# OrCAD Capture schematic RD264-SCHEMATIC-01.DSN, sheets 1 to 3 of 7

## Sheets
1 7: size A3
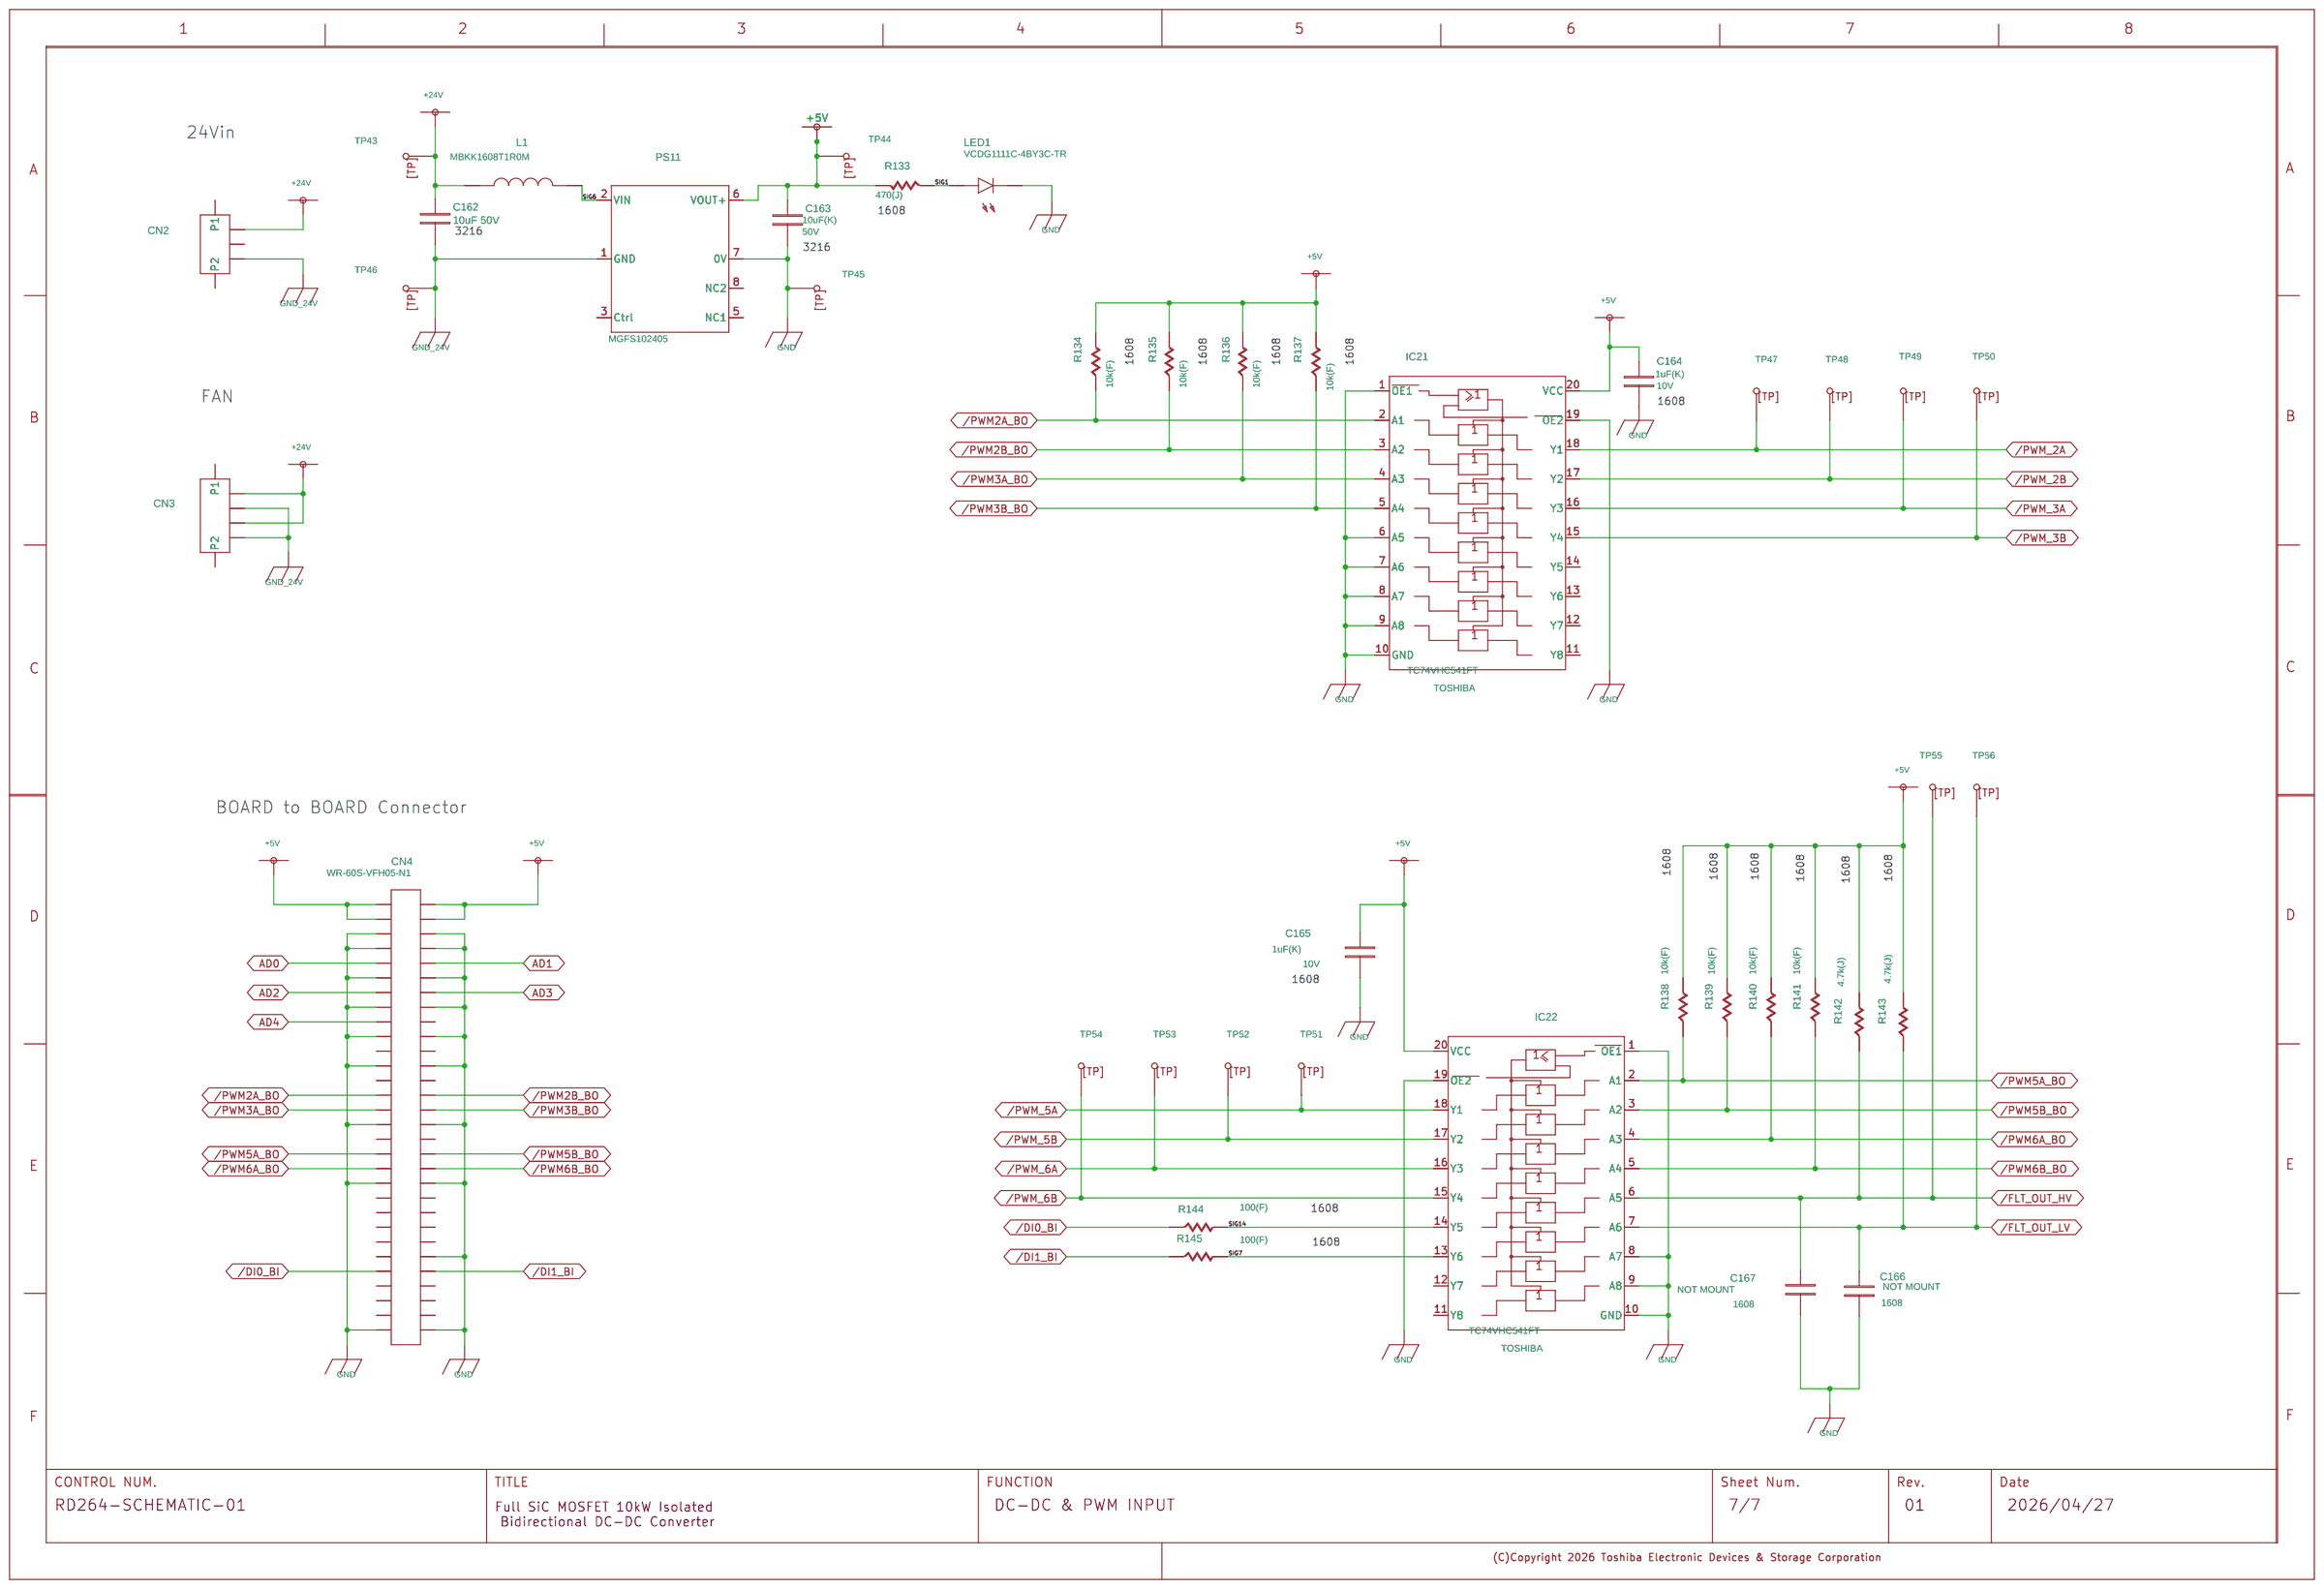
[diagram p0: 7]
2 6: size A3
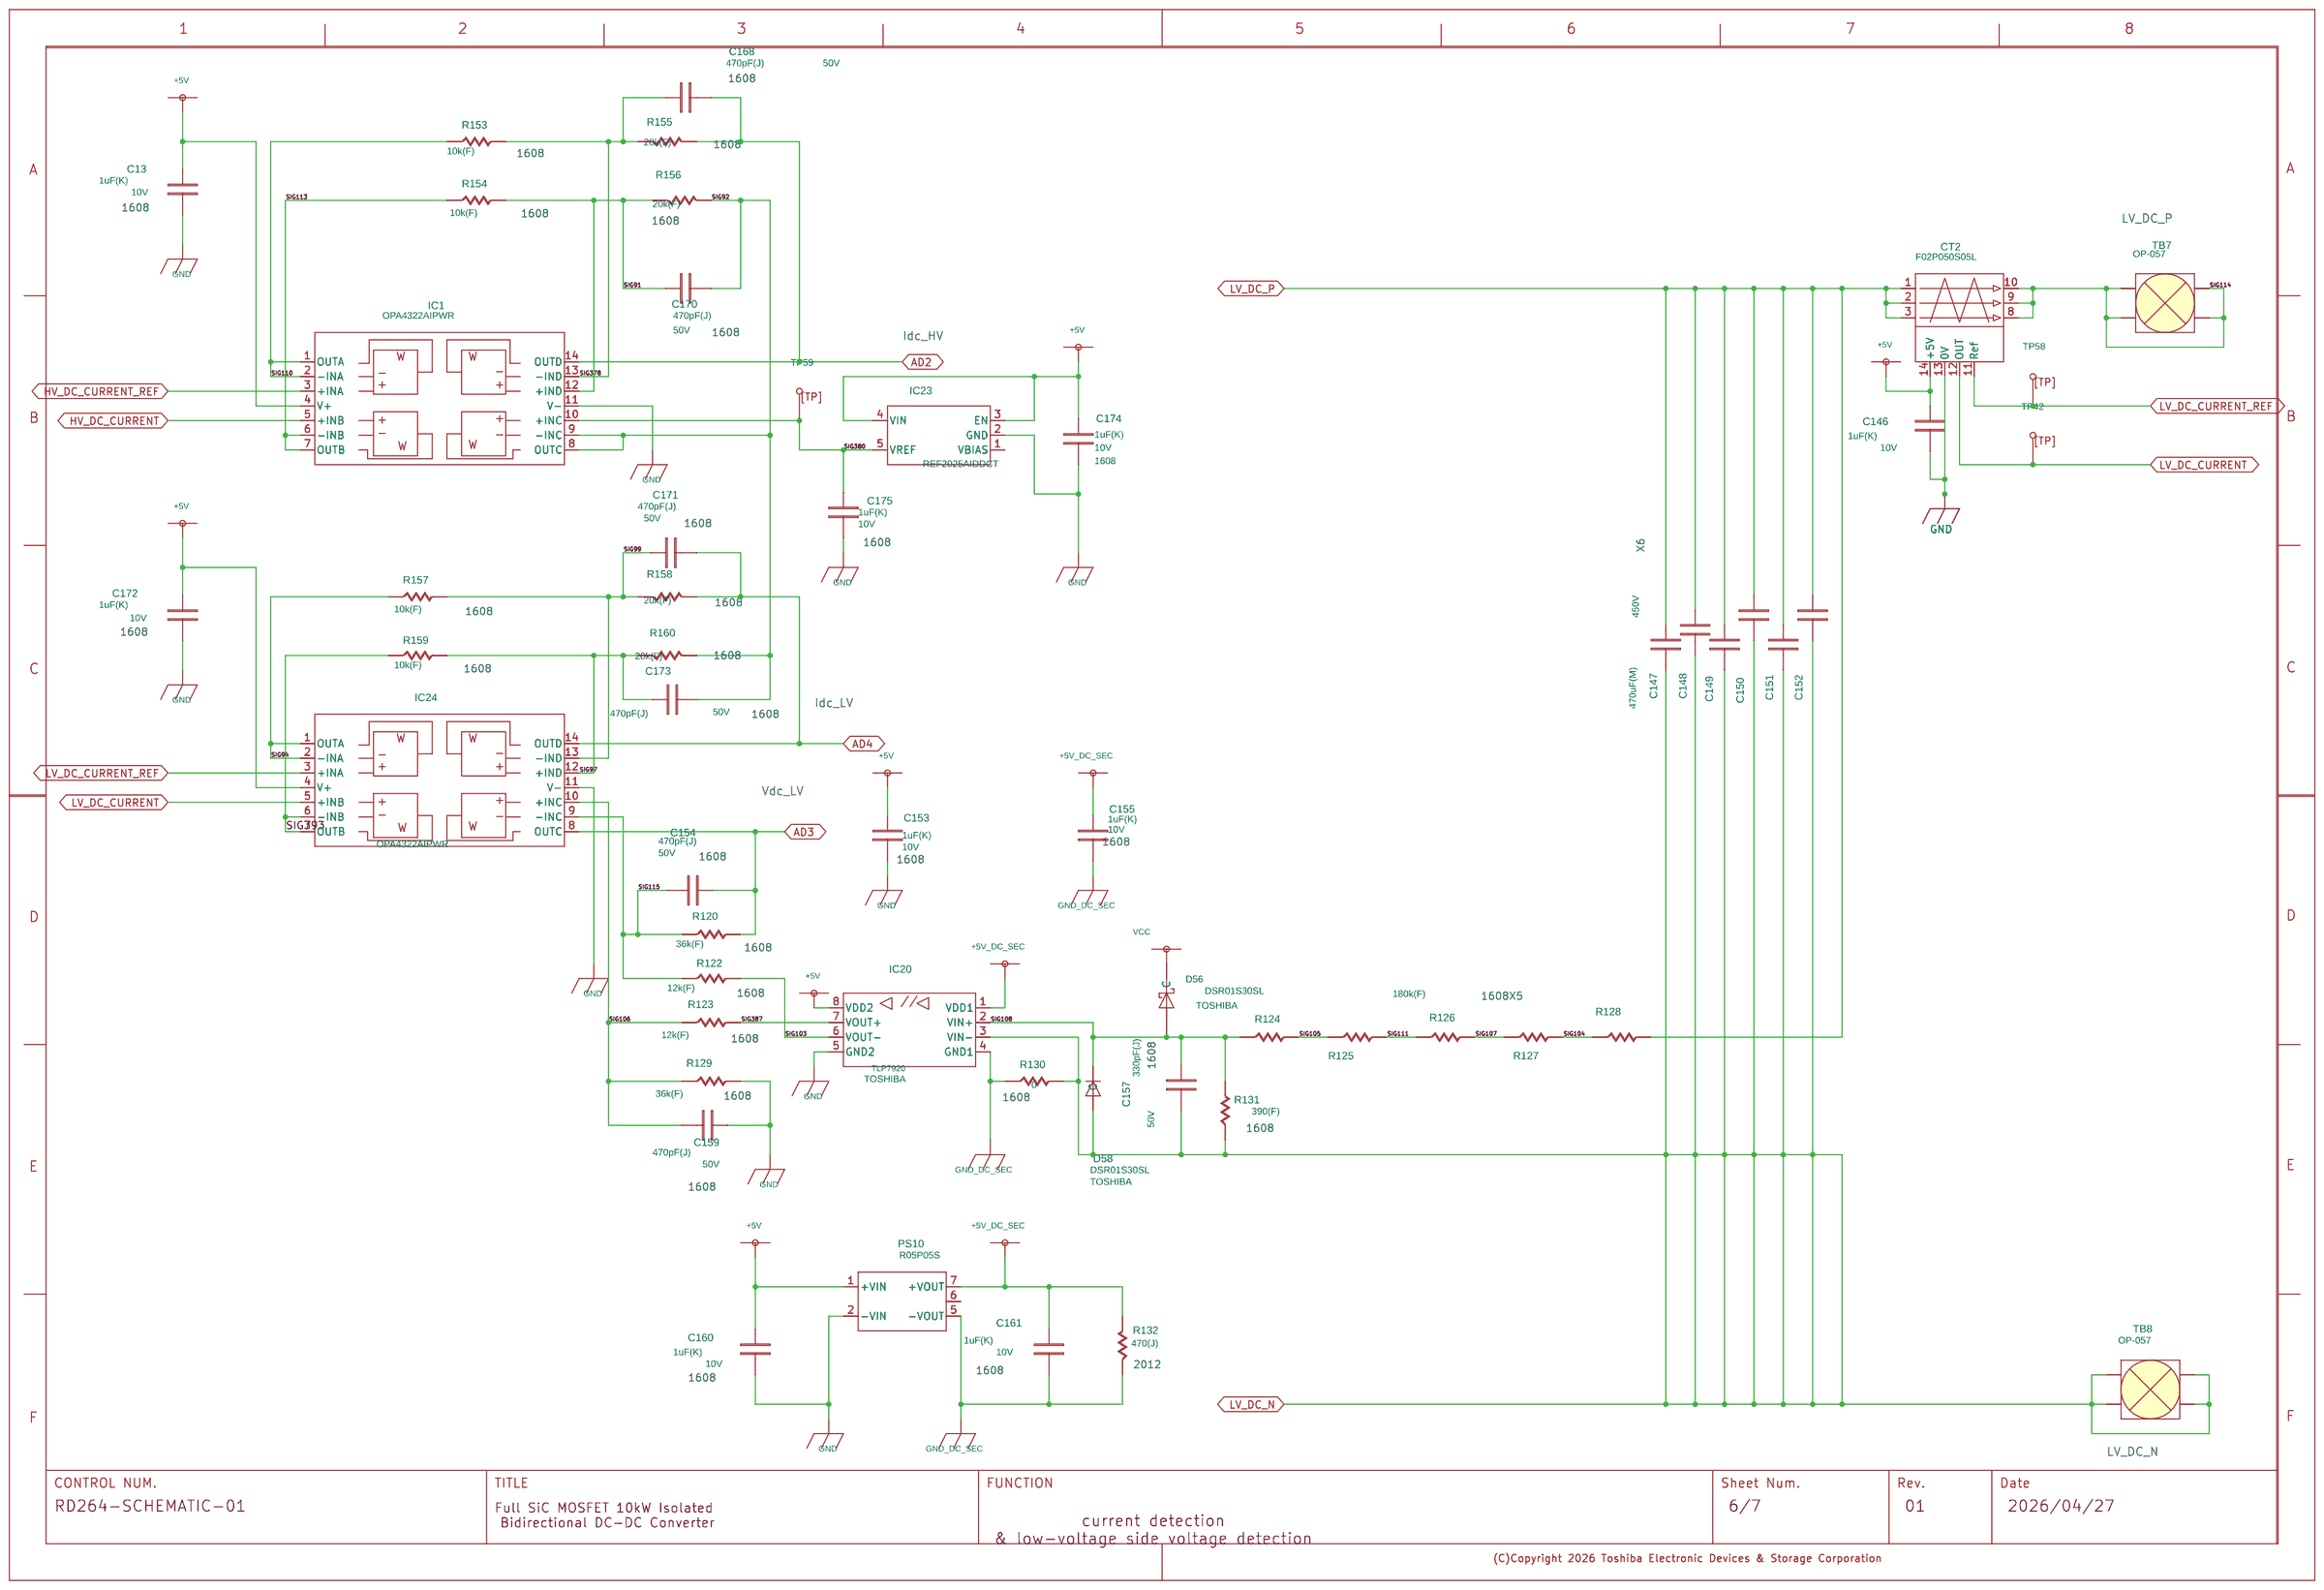
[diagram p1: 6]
3 5: size A3
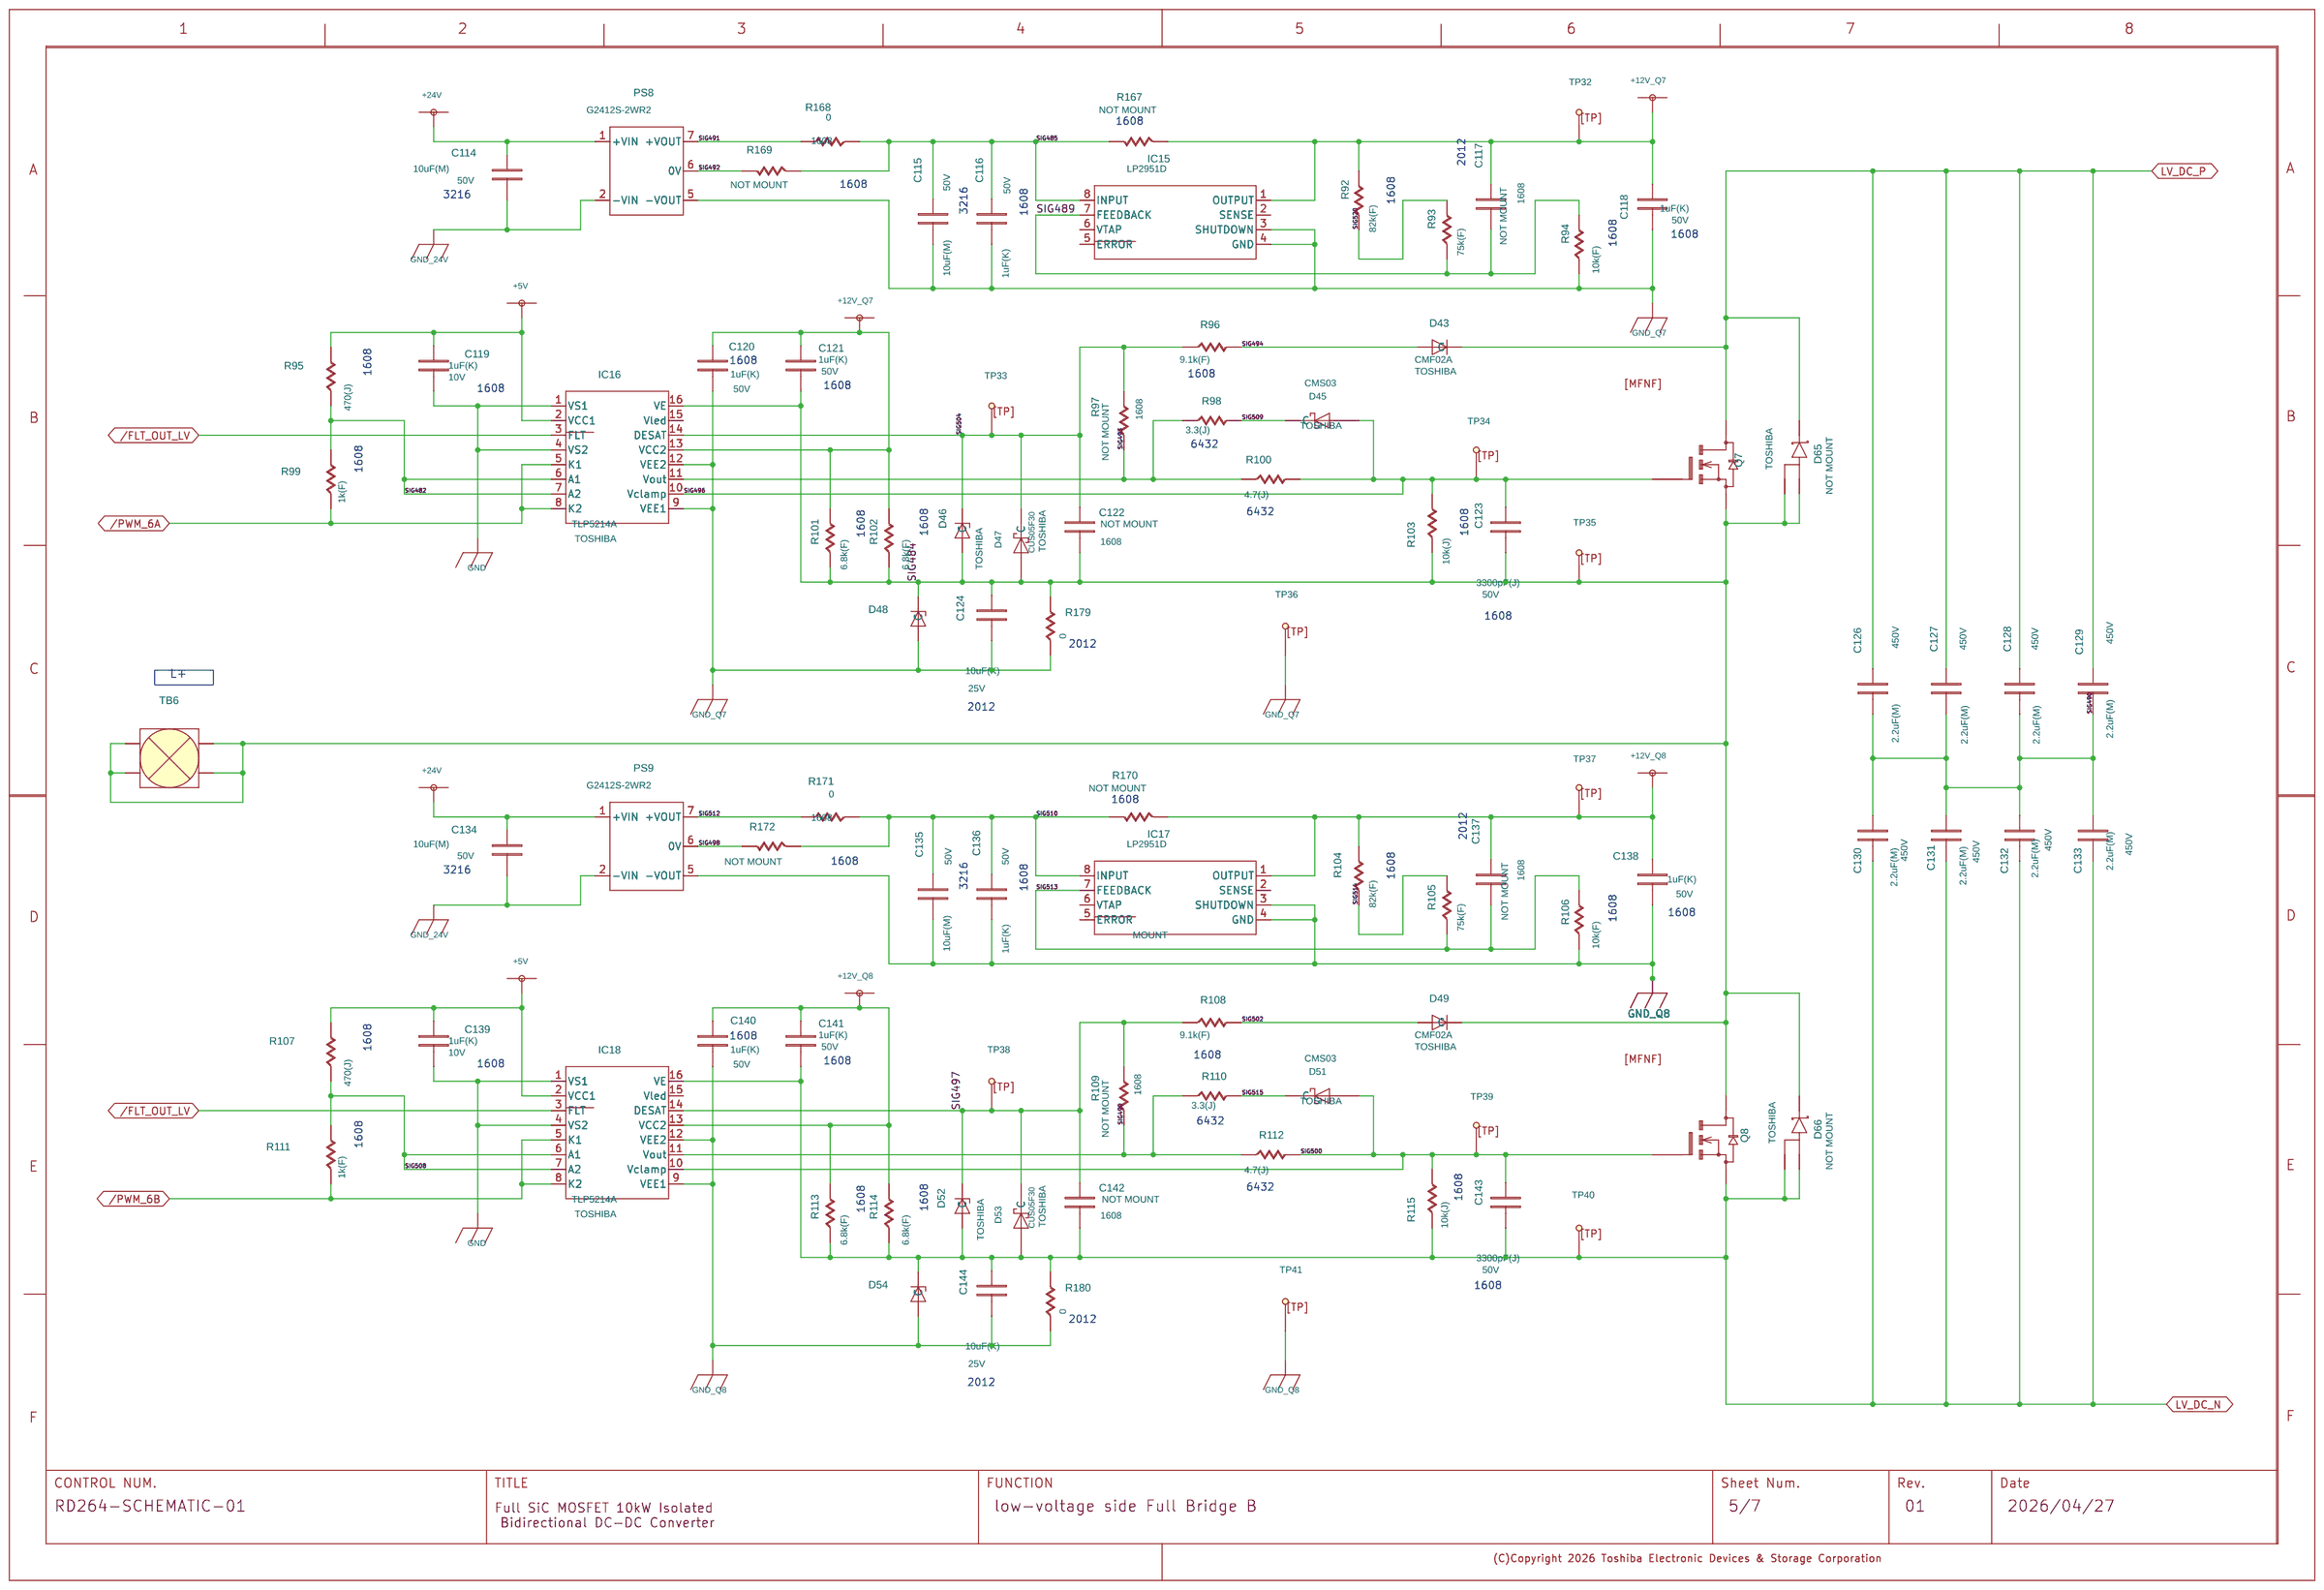
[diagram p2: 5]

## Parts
sheet 5
C114  GRM31CR61H106MA12L
C115  GRM31CR61H106MA12L
C116  GRM188R61H105KAALD
C117  NC_C1608
C118  GRM188R61H105KAALD
C119  GRM188R71A105KA61D
C120  GRM188R61H105KAALD
C121  GRM188R61H105KAALD
C122  NC_C1608
C123  GRM1885C1H682JA01D
C124  GRM21BC71E106KE11L
C126  CKG57NX7T2W225M500JH
C127  CKG57NX7T2W225M500JH
C128  CKG57NX7T2W225M500JH
C129  CKG57NX7T2W225M500JH
C130  CKG57NX7T2W225M500JH
C131  CKG57NX7T2W225M500JH
C132  CKG57NX7T2W225M500JH
C133  CKG57NX7T2W225M500JH
C134  GRM31CR61H106MA12L
C135  GRM31CR61H106MA12L
C136  GRM188R61H105KAALD
C137  NC_C1608
C138  GRM188R61H105KAALD
C139  GRM188R71A105KA61D
C140  GRM188R61H105KAALD
C141  GRM188R61H105KAALD
C142  NC_C1608
C143  GRM1885C1H682JA01D
C144  GRM21BC71E106KE11L
D43  CMF05
D45  SBD
D46  CRY82
D47  SBD
D48  KDZVTR2.0B
D49  CMF05
D51  SBD
D52  CRY82
D53  SBD
D54  KDZVTR2.0B
D65  NC_TO-247
D66  NC_TO-247
IC15  LP2951D
IC16  TLP5214A
IC17  LP2951D
IC18  TLP5214A
PS8  G2412S-2WR2
PS9  G2412S-2WR2
Q7  TK49N65W5
Q8  TK49N65W5
R92  RK73H1JTTD8202F
R93  RK73H1JTTD7502F
R94  RK73H1JTTD1002F
R95  RK73B1JTTD471J
R96  ERJ3EKF9101V
R97  NC_R1608
R98  ERJ1TYJ100U
R99  RK73H1JTTD1001F
R100  ERJ1TYJ470U
R101  RK73H1JTTD6801F
R102  RK73H1JTTD6801F
R103  RK73B1JTTD103J
R104  RK73H1JTTD8202F
R105  RK73H1JTTD7502F
R106  RK73H1JTTD1002F
R107  RK73B1JTTD471J
R108  ERJ3EKF9101V
R109  NC_R1608
R110  ERJ1TYJ100U
R111  RK73H1JTTD1001F
R112  ERJ1TYJ470U
R113  RK73H1JTTD6801F
R114  RK73H1JTTD6801F
R115  RK73B1JTTD103J
R167  RK73Z1JTTD
R168  NC_R1608
R169  RK73Z1JTTD
R170  RK73Z1JTTD
R171  NC_R1608
R172  RK73Z1JTTD
R179  RK73Z2ATTD
R180  RK73Z2ATTD
TB6  OP-057
TP32  TP
TP33  TP
TP34  TP
TP35  TP
TP36  TP
TP37  TP
TP38  TP
TP39  TP
TP40  TP
TP41  TP
U?#2  WAKU_DEF100
sheet 6
C13  GRM188R71A105KA61D
C146  GRM188R71A105KA61D
C147  ESMR451VSN471MR40S
C148  ESMR451VSN471MR40S
C149  ESMR451VSN471MR40S
C150  ESMR451VSN471MR40S
C151  ESMR451VSN471MR40S
C152  ESMR451VSN471MR40S
C153  GRM188R71A105KA61D
C154  GRM1885C1H471JA01D
C155  GRM188R71A105KA61D
C157  GRM1885C1H331JA01D
C159  GRM1885C1H471JA01D
C160  GRM188R71A105KA61D
C161  GRM188R71A105KA61D
C168  GRM1885C1H471JA01D
C170  GRM1885C1H471JA01D
C171  GRM1885C1H471JA01D
C172  GRM188R71A105KA61D
C173  GRM1885C1H471JA01D
C174  GRM188R71A105KA61D
C175  GRM188R71A105KA61D
CT2  F02P050S05L
D56  SBD
D58  DSR01S30SL
IC1  OPA4322AIPWR
IC20  TLP7920(LF5,TP5)
IC23  REF2025AIDDCT
IC24  OPA4322AIPWR
PS10  R05P05S
R120  RK73G1JTTD3602F
R122  RK73G1JTTD1202F
R123  RK73G1JTTD1202F
R124  ERJ3EKF1803V
R125  ERJ3EKF1803V
R126  ERJ3EKF1803V
R127  ERJ3EKF1803V
R128  ERJ3EKF1803V
R129  RK73G1JTTD3602F
R130  RK73Z1JTTD
R131  RK73G1JTTD3900F
R132  RK73B2ATTD471J
R153  RK73H1JTTD1002F
R154  RK73H1JTTD1002F
R155  RK73H1JTTD2002F
R156  RK73H1JTTD2002F
R157  RK73H1JTTD1002F
R158  RK73H1JTTD2002F
R159  RK73H1JTTD1002F
R160  RK73H1JTTD2002F
TB7  OP-057
TB8  OP-057
TP42  TP
TP58  TP
TP59  TP
U?#1  WAKU_DEF100
sheet 7
C162  GRM31CR61H106KA12L
C163  GRM31CR61H106KA12L
C164  GRM188R71A105KA61D
C165  GRM188R71A105KA61D
C166  NC_C1608
C167  NC_C1608
CN2  BM03B-PASS-TFT(LF)(SN)
CN3  BM04B-PASS-TFT(LF)(SN)
CN4  WR-60S-VFH05-N1
IC21  TC74VHC541FT
IC22  TC74VHC541FT
L1  MBKK1608T1R0M
LED1  VCDG1111C-4BY3C-TR
PS11  MGFS102405
R133  RK73B1JTTD471J
R134  RK73H1JTTD1002F
R135  RK73H1JTTD1002F
R136  RK73H1JTTD1002F
R137  RK73H1JTTD1002F
R138  RK73H1JTTD1002F
R139  RK73H1JTTD1002F
R140  RK73H1JTTD1002F
R141  RK73H1JTTD1002F
R142  RK73B1JTTD472J
R143  RK73B1JTTD472J
R144  ERJ3EKF1000V
R145  ERJ3EKF1000V
TP43  TP
TP44  TP
TP45  TP
TP46  TP
TP47  TP
TP48  TP
TP49  TP
TP50  TP
TP51  TP
TP52  TP
TP53  TP
TP54  TP
TP55  TP
TP56  TP
U?#7  WAKU_DEF100

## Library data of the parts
C114 C134 = C_v2: COMP: C-GRM31CR61H106MA12L; COMPONENTNAME: C_C.Normal_package; COMPONENTTYPE: 4; FUNCN: C_C.Normal_package; INSTANCENAME: INS17112921; NOTE: 10uF 50V; PART TYPE: Ceramic Capacitor; REFERENCE TEMPLATE: C; SIZE: 1; VAL1: 10uF(M); VAL2: 50V
C115 C135 = C_v2: COMP: C-GRM31CR61H106MA12L; COMPONENTNAME: C_C.Normal_package; COMPONENTTYPE: 4; FUNCN: C_C.Normal_package; INSTANCENAME: INS17112929; NOTE: 10uF 50V; PART TYPE: Ceramic Capacitor; REFERENCE TEMPLATE: C; SIZE: 1; VAL1: 10uF(M); VAL2: 50V
C116 C136 = C_v2: COMP: C-GRM188R61H105KAALD; COMPONENTNAME: C_C.Normal_package; COMPONENTTYPE: 4; FUNCN: C_C.Normal_package; INSTANCENAME: INS17112937; NOTE: 1uF 50V; PART TYPE: Ceramic Capacitor; REFERENCE TEMPLATE: C; SIZE: 1; VAL1: 1uF(K); VAL2: 50V
C117 C137 = C_v2: COMP: C-1608_NM; COMPONENTNAME: C_C.Normal_package; COMPONENTTYPE: 4; FUNCN: C_C.Normal_package; INSTANCENAME: INS17112913; NOTMOUNT: NOT MOUNT; PART TYPE: Ceramic Capacitor; REFERENCE TEMPLATE: C; SIZE: 1; SIZECODESMD: 1608
C118 C138 = C_v2: COMP: C-GRM188R61H105KAALD; COMPONENTNAME: C_C.Normal_package; COMPONENTTYPE: 4; FUNCN: C_C.Normal_package; INSTANCENAME: INS17112961; NOTE: 1uF 50V; PART TYPE: Ceramic Capacitor; REFERENCE TEMPLATE: C; SIZE: 1; VAL1: 1uF(K); VAL2: 50V
C119 C139 = C_v2: COMP: C-GRM188R71A105KA61D; COMPONENTNAME: C_C.Normal_package; COMPONENTTYPE: 4; FUNCN: C_C.Normal_package; INSTANCENAME: INS17113085; NOTE: 1uF 10V; PART TYPE: Ceramic Capacitor; REFERENCE TEMPLATE: C; SIZE: 1; VAL1: 1uF(K); VAL2: 10V
C120 C140 = C_v2: COMP: C-GRM188R61H105KAALD; COMPONENTNAME: C_C.Normal_package; COMPONENTTYPE: 4; FUNCN: C_C.Normal_package; INSTANCENAME: INS17113061; NOTE: 1uF 50V; PART TYPE: Ceramic Capacitor; REFERENCE TEMPLATE: C; SIZE: 1; VAL1: 1uF(K); VAL2: 50V
C121 C141 = C_v2: COMP: C-GRM188R61H105KAALD; COMPONENTNAME: C_C.Normal_package; COMPONENTTYPE: 4; FUNCN: C_C.Normal_package; INSTANCENAME: INS17113069; NOTE: 1uF 50V; PART TYPE: Ceramic Capacitor; REFERENCE TEMPLATE: C; SIZE: 1; VAL1: 1uF(K); VAL2: 50V
C122 C142 = C_v2: COMP: C-1608_NM; COMPONENTNAME: C_C.Normal_package; COMPONENTTYPE: 4; FUNCN: C_C.Normal_package; INSTANCENAME: INS17113388; NOTMOUNT: NOT MOUNT; PART TYPE: Ceramic Capacitor; REFERENCE TEMPLATE: C; SIZE: 1; SIZECODESMD: 1608
C123 C143 = C_v2: COMP: C-GRM1885C1H682JA01D; COMPONENTNAME: C_C.Normal_package; COMPONENTTYPE: 4; FUNCN: C_C.Normal_package; INSTANCENAME: INS17753463; NOTE: 6800pF 50V; PART TYPE: Ceramic Capacitor; REFERENCE TEMPLATE: C; SIZE: 1; VAL1: 3300pF(J); VAL2: 50V
C124 C144 = C_v2: COMP: C-GRM21BC71E106KE11L; COMPONENTNAME: C_C.Normal_package; COMPONENTTYPE: 4; FUNCN: C_C.Normal_package; INSTANCENAME: INS17895207; NOTE: 10uF 25V; PART TYPE: Ceramic Capacitor; REFERENCE TEMPLATE: C; SIZE: 1; VAL1: 10uF(K); VAL2: 25V
C126 = C_v2: COMP: C-CKG57NX7T2W225M500JH; COMPONENTNAME: C_C.Normal_package; COMPONENTTYPE: 4; FUNCN: C_C.Normal_package; INSTANCENAME: INS17255321; NOTE: 2.2uF 450V; PART TYPE: Ceramic Capacitor; REFERENCE TEMPLATE: C; SIZE: 1; VAL1: 2.2uF(M); VAL2: 450V
C127 = C_v2: COMP: C-CKG57NX7T2W225M500JH; COMPONENTNAME: C_C.Normal_package; COMPONENTTYPE: 4; FUNCN: C_C.Normal_package; INSTANCENAME: INS17255582; NOTE: 2.2uF 450V; PART TYPE: Ceramic Capacitor; REFERENCE TEMPLATE: C; SIZE: 1; VAL1: 2.2uF(M); VAL2: 450V
C128 = C_v2: COMP: C-CKG57NX7T2W225M500JH; COMPONENTNAME: C_C.Normal_package; COMPONENTTYPE: 4; FUNCN: C_C.Normal_package; INSTANCENAME: INS17255645; NOTE: 2.2uF 450V; PART TYPE: Ceramic Capacitor; REFERENCE TEMPLATE: C; SIZE: 1; VAL1: 2.2uF(M); VAL2: 450V
C129 = C_v2: COMP: C-CKG57NX7T2W225M500JH; COMPONENTNAME: C_C.Normal_package; COMPONENTTYPE: 4; FUNCN: C_C.Normal_package; INSTANCENAME: INS17255762; NOTE: 2.2uF 450V; PART TYPE: Ceramic Capacitor; REFERENCE TEMPLATE: C; SIZE: 1; VAL1: 2.2uF(M); VAL2: 450V
C130 = C_v2: COMP: C-CKG57NX7T2W225M500JH; COMPONENTNAME: C_C.Normal_package; COMPONENTTYPE: 4; FUNCN: C_C.Normal_package; INSTANCENAME: INS17255916; NOTE: 2.2uF 450V; PART TYPE: Ceramic Capacitor; REFERENCE TEMPLATE: C; SIZE: 1; VAL1: 2.2uF(M); VAL2: 450V
C131 = C_v2: COMP: C-CKG57NX7T2W225M500JH; COMPONENTNAME: C_C.Normal_package; COMPONENTTYPE: 4; FUNCN: C_C.Normal_package; INSTANCENAME: INS17256105; NOTE: 2.2uF 450V; PART TYPE: Ceramic Capacitor; REFERENCE TEMPLATE: C; SIZE: 1; VAL1: 2.2uF(M); VAL2: 450V
C132 = C_v2: COMP: C-CKG57NX7T2W225M500JH; COMPONENTNAME: C_C.Normal_package; COMPONENTTYPE: 4; FUNCN: C_C.Normal_package; INSTANCENAME: INS17256431; NOTE: 2.2uF 450V; PART TYPE: Ceramic Capacitor; REFERENCE TEMPLATE: C; SIZE: 1; VAL1: 2.2uF(M); VAL2: 450V
C133 = C_v2: COMP: C-CKG57NX7T2W225M500JH; COMPONENTNAME: C_C.Normal_package; COMPONENTTYPE: 4; FUNCN: C_C.Normal_package; INSTANCENAME: INS17256618; NOTE: 2.2uF 450V; PART TYPE: Ceramic Capacitor; REFERENCE TEMPLATE: C; SIZE: 1; VAL1: 2.2uF(M); VAL2: 450V
D43 D49 = D: COMP: D-CMF05; COMPONENTNAME: D_D.Normal_package; COMPONENTTYPE: 4; FUNCN: D_D.Normal_package; INSTANCENAME: INS17279788; USERCOMPTEXT3: TOSHIBA; VAL3: CMF02A
D45 D51 = SBD: COMP: CMS03; COMPONENTTYPE: 4; USERCOMPTEXT3: TOSHIBA; VAL3: CMS03
D46 D52 = ZD: COMP: D-CRY82; COMPONENTNAME: ZD_ZD.Normal_package; COMPONENTTYPE: 4; FUNCN: ZD_ZD.Normal_package; INSTANCENAME: INS17317417; USERCOMPTEXT3: TOSHIBA
D47 D53 = SBD: COMP: CUS05F30; COMPONENTTYPE: 4; USERCOMPTEXT3: TOSHIBA; VAL3: CUS05F30
D48 D54 = ZD: COMP: D-KDZVTR2.0B; COMPONENTNAME: ZD_ZD.Normal_package; COMPONENTTYPE: 4; FUNCN: ZD_ZD.Normal_package; INSTANCENAME: INS17385836; PART TYPE: Zener diode; REFERENCE TEMPLATE: D
D65 D66 = NC_TO_247: COMP: D-TO-247_NM; COMPONENTNAME: NC_TO-247_NC_TO-247.Normal_package; COMPONENTTYPE: 4; FUNCN: NC_TO-247_NC_TO-247.Normal_package; INSTANCENAME: INS17322987; NOTMOUNT: NOT MOUNT; SAVECOUNT: 1; UPDATEDATE: 2020/05/13; UPDATETIME: 14:31:25; VAL3: TO-247
IC15 IC17 = LP2951D: COMP: IC-LP2951D_NM; COMPONENTTYPE: 4; NOTMOUNT: MOUNT
IC16 IC18 = TLP5214A: COMP: IC-TLP5214A; COMPONENTTYPE: 4; USERCOMPTEXT3: TOSHIBA
PS8 PS9 = G2412S_2WR2: COMP: PS-G2412S-2WR2; COMPONENTTYPE: 4
Q7 Q8 = MFNF: COMP: TW048N65C; COMPONENTNAME: MFNF_MFNF.Normal_package; COMPONENTTYPE: 4; FUNCN: MFNF_MFNF.Normal_package; INSTANCENAME: INS17254361; PART NUMBER: TMP-432; PART TYPE: N-channel  Si power MOSFET; REFERENCE TEMPLATE: Q; USERCOMPTEXT3: TOSHIBA; VAL3: TW048N65C
R92 R104 = R: COMP: R-RK73H1JTTD8202F; COMPONENTNAME: R_R.Normal_package; COMPONENTTYPE: 4; FUNCN: R_R.Normal_package; INSTANCENAME: INS17112901; NOTE: 82kohm 0.1W; VAL1: 82k(F); VAL2: 100mw
R93 R105 = R: COMP: R-RK73H1JTTD7502F; COMPONENTNAME: R_R.Normal_package; COMPONENTTYPE: 4; FUNCN: R_R.Normal_package; INSTANCENAME: INS17112949; NOTE: 75kohm 0.1W; VAL1: 75k(F); VAL2: 100mw
R94 R106 = R: COMP: R-RK73H1JTTD1002F; COMPONENTNAME: R_R.Normal_package; COMPONENTTYPE: 4; FUNCN: R_R.Normal_package; INSTANCENAME: INS17112973; NOTE: 10kohm 0.1W; VAL1: 10k(F); VAL2: 100mw
R95 R107 = R: COMP: R-RK73B1JTTD471J; COMPONENTNAME: R_R.Normal_package; COMPONENTTYPE: 4; FUNCN: R_R.Normal_package; INSTANCENAME: INS17113077; NOTE: 470ohm 0.1W; PART TYPE: Resistor SMD; SIZE: 1; VAL1: 470(J); VAL2: 125mw
R96 R108 = R: COMP: R-ERJ3EKF9101V; COMPONENTNAME: R_R.Normal_package; COMPONENTTYPE: 4; FUNCN: R_R.Normal_package; INSTANCENAME: INS17253791; NOTE: 9.1kohm 0.1W; PART NUMBER: TMP-429; PART TYPE: Resistor SMD; VAL1: 9.1k(F); VAL2: 100mw
R97 R109 = R: COMP: R-1608_NM; COMPONENTNAME: R_R.Normal_package; COMPONENTTYPE: 4; FUNCN: R_R.Normal_package; INSTANCENAME: INS17113188; NOTMOUNT: NOT MOUNT; PART TYPE: Resistor SMD; SIZE: 1; SIZECODESMD: 1608
R98 R110 = R: COMP: R-ERJ1TYJ100U; COMPONENTNAME: R_R.Normal_package; COMPONENTTYPE: 4; FUNCN: R_R.Normal_package; INSTANCENAME: INS17253884; NOTE: 10ohm 1W; PART TYPE: Resistor SMD; SIZE: 1; VAL1: 3.3(J); VAL2: 1w
R99 R111 = R: COMP: R-RK73H1JTTD1001F; COMPONENTNAME: R_R.Normal_package; COMPONENTTYPE: 4; FUNCN: R_R.Normal_package; INSTANCENAME: INS17113262; NOTE: 1.0kohm 0.1W; PART TYPE: Resistor SMD; SIZE: 1; VAL1: 1k(F); VAL2: 125mw
R100 R112 = R: COMP: R-ERJ1TYJ470U; COMPONENTNAME: R_R.Normal_package; COMPONENTTYPE: 4; FUNCN: R_R.Normal_package; INSTANCENAME: INS17753183; NOTE: 47ohm 1W; PART NUMBER: TMP-902; PART TYPE: Resistor SMD; VAL1: 4.7(J); VAL2: 1w
R101 R113 = R: COMP: R-RK73H1JTTD6801F; COMPONENTNAME: R_R.Normal_package; COMPONENTTYPE: 4; FUNCN: R_R.Normal_package; INSTANCENAME: INS17113356; NOTE: 6.8kohm 0.1W; PART TYPE: Resistor SMD; SIZE: 1; VAL1: 6.8k(F); VAL2: 100mw
R102 R114 = R: COMP: R-RK73H1JTTD6801F; COMPONENTNAME: R_R.Normal_package; COMPONENTTYPE: 4; FUNCN: R_R.Normal_package; INSTANCENAME: INS17113364; NOTE: 6.8kohm 0.1W; PART TYPE: Resistor SMD; SIZE: 1; VAL1: 6.8k(F); VAL2: 100mw
R103 R115 = R: COMP: R-RK73B1JTTD103J; COMPONENTNAME: R_R.Normal_package; COMPONENTTYPE: 4; FUNCN: R_R.Normal_package; INSTANCENAME: INS17113334; NOTE: 10kohm 0.1W; PART TYPE: Resistor SMD; SIZE: 1; VAL1: 10k(J); VAL2: 100mw
R167 R170 = R: COMP: R-RK73Z1JTTD; COMPONENTNAME: R_R.Normal_package; COMPONENTTYPE: 4; FUNCN: R_R.Normal_package; INSTANCENAME: INS17390327; NOTE: 0ohm 0.1W; NOTMOUNT: NOT MOUNT; PART TYPE: Resistor SMD; SIZE: 1
R168 = R: COMP: R-1608_NM; COMPONENTNAME: R_R.Normal_package; COMPONENTTYPE: 4; FUNCN: R_R.Normal_package; INSTANCENAME: INS17391865; NOTMOUNT: MOUNT; PART TYPE: Resistor SMD; SIZE: 1; VAL1: 0; VAL3: 1608
R169 R172 = R: COMP: R-RK73Z1JTTD; COMPONENTNAME: R_R.Normal_package; COMPONENTTYPE: 4; FUNCN: R_R.Normal_package; INSTANCENAME: INS17391891; NOTE: 0ohm 0.1W; NOTMOUNT: NOT MOUNT; PART TYPE: Resistor SMD; SIZE: 1
R171 = R: COMP: R-1608_NM; COMPONENTNAME: R_R.Normal_package; COMPONENTTYPE: 4; FUNCN: R_R.Normal_package; INSTANCENAME: INS17391865; NOTMOUNT: MOUNT; PART TYPE: Resistor SMD; SIZE: 1; SIZECODESMD: 1608; VAL1: 0
R179 R180 = R: COMP: R-RK73Z2ATTD; COMPONENTNAME: R_R.Normal_package; COMPONENTTYPE: 4; FUNCN: R_R.Normal_package; INSTANCENAME: INS17894887; NOTE: 0ohm 0.25w; PART TYPE: Resistor SMD; SIZE: 1; VAL1: 0
TB6 = OP_057: COMP: TB-OP-057; COMPONENTNAME: OP-057_OP-057.Normal_package; COMPONENTTYPE: 4; FUNCN: OP-057_OP-057.Normal_package; INSTANCENAME: INS17364097; PART NUMBER: TMP-784; PART TYPE: Terminal Block; REFERENCE TEMPLATE: TB; SAVECOUNT: 1; UPDATETIME: 14:31:25
TP32-TP56 TP58 TP59 = TP: COMP: TP-HK-3-G; COMPONENTTYPE: 4; VAL3: HK-3-G
U?#2 = WAKU_DEF100: COMPONENTTYPE: 2; DATE: 2026/04/27; DRAWINGNUMBER: RD264-SCHEMATIC-01; FUNCTION: low-voltage side Full Bridge B; REVISION: 01; SHEETNUMBER: 5/7; SHTSAVECOUNT: 17; TITLE: Full SiC MOSFET 10kW Isolated / Bidirectional DC-DC Converter; UPDATEDATE: 2026.4.27; UPDATETIME: 14:22:34
C13 C172 = C_v2: COMP: C-GRM188R71A105KA61D; COMPONENTNAME: C_C.Normal_package; COMPONENTTYPE: 4; FUNCN: C_C.Normal_package; INSTANCENAME: INS17335180; NOTE: 1uF 10V; PART TYPE: Ceramic Capacitor; REFERENCE TEMPLATE: C; SIZE: 1; VAL1: 1uF(K); VAL2: 10V
C146 = C_v2: COMP: C-GRM188R71A105KA61D; COMPONENTNAME: C_C.Normal_package; COMPONENTTYPE: 4; FUNCN: C_C.Normal_package; INSTANCENAME: INS17154372; NOTE: 1uF 10V; PART TYPE: Ceramic Capacitor; REFERENCE TEMPLATE: C; SIZE: 1; VAL1: 1uF(K); VAL2: 10V
C147 = C_v2: COMP: C-ESMR451VSN471MR40S; COMPONENTNAME: C_C.Normal_package; COMPONENTTYPE: 4; FUNCN: C_C.Normal_package; INSTANCENAME: INS17110408; NOTE: 470uF 450V; PART TYPE: Aluminum Capacitor; REFERENCE TEMPLATE: C; SIZE: 1; VAL1: 470uF(M); VAL2: 450V
C148 = C_v2: COMP: C-ESMR451VSN471MR40S; COMPONENTNAME: C_C.Normal_package; COMPONENTTYPE: 4; FUNCN: C_C.Normal_package; INSTANCENAME: INS17110416; NOTE: 470uF 450V; PART TYPE: Aluminum Capacitor; REFERENCE TEMPLATE: C; SIZE: 1; VAL1: 470uF(M); VAL2: 450V
C149 = C_v2: COMP: C-ESMR451VSN471MR40S; COMPONENTNAME: C_C.Normal_package; COMPONENTTYPE: 4; FUNCN: C_C.Normal_package; INSTANCENAME: INS17110424; NOTE: 470uF 450V; PART TYPE: Aluminum Capacitor; REFERENCE TEMPLATE: C; SIZE: 1; VAL1: 470uF(M); VAL2: 450V
C150 = C_v2: COMP: C-ESMR451VSN471MR40S; COMPONENTNAME: C_C.Normal_package; COMPONENTTYPE: 4; FUNCN: C_C.Normal_package; INSTANCENAME: INS17110469; NOTE: 470uF 450V; PART TYPE: Aluminum Capacitor; REFERENCE TEMPLATE: C; SIZE: 1; VAL1: 470uF(M); VAL2: 450V
C151 = C_v2: COMP: C-ESMR451VSN471MR40S; COMPONENTNAME: C_C.Normal_package; COMPONENTTYPE: 4; FUNCN: C_C.Normal_package; INSTANCENAME: INS17110477; NOTE: 470uF 450V; PART TYPE: Aluminum Capacitor; REFERENCE TEMPLATE: C; SIZE: 1; VAL1: 470uF(M); VAL2: 450V
C152 = C_v2: COMP: C-ESMR451VSN471MR40S; COMPONENTNAME: C_C.Normal_package; COMPONENTTYPE: 4; FUNCN: C_C.Normal_package; INSTANCENAME: INS17110485; NOTE: 470uF 450V; PART TYPE: Aluminum Capacitor; REFERENCE TEMPLATE: C; SIZE: 1; VAL1: 470uF(M); VAL2: 450V
C153 C155 = C_v2: COMP: C-GRM188R71A105KA61D; COMPONENTNAME: C_C.Normal_package; COMPONENTTYPE: 4; FUNCN: C_C.Normal_package; INSTANCENAME: INS17110613; NOTE: 1uF 10V; PART TYPE: Ceramic Capacitor; REFERENCE TEMPLATE: C; SIZE: 1; VAL1: 1uF(K); VAL2: 10V
C154 = C_v2: COMP: C-GRM1885C1H471JA01D; COMPONENTNAME: C_C.Normal_package; COMPONENTTYPE: 4; FUNCN: C_C.Normal_package; INSTANCENAME: INS17110583; NOTE: 470pF 50V; PART TYPE: Ceramic Capacitor; REFERENCE TEMPLATE: C; SIZE: 1; VAL1: 470pF(J); VAL2: 50V
C157 = C_v2: COMP: C-GRM1885C1H331JA01D; COMPONENTNAME: C_C.Normal_package; COMPONENTTYPE: 4; FUNCN: C_C.Normal_package; INSTANCENAME: INS17110887; NOTE: 330pF 50V; PART TYPE: Ceramic Capacitor; REFERENCE TEMPLATE: C; SIZE: 1; VAL1: 330pF(J); VAL2: 50V
C159 = C_v2: COMP: C-GRM1885C1H471JA01D; COMPONENTNAME: C_C.Normal_package; COMPONENTTYPE: 4; FUNCN: C_C.Normal_package; INSTANCENAME: INS17110939; NOTE: 470pF 50V; PART TYPE: Ceramic Capacitor; REFERENCE TEMPLATE: C; SIZE: 1; VAL1: 470pF(J); VAL2: 50V
C160 = C_v2: COMP: C-GRM188R71A105KA61D; COMPONENTNAME: C_C.Normal_package; COMPONENTTYPE: 4; FUNCN: C_C.Normal_package; INSTANCENAME: INS17111029; NOTE: 1uF 10V; PART TYPE: Ceramic Capacitor; REFERENCE TEMPLATE: C; SIZE: 1; VAL1: 1uF(K); VAL2: 10V
C161 = C_v2: COMP: C-GRM188R71A105KA61D; COMPONENTNAME: C_C.Normal_package; COMPONENTTYPE: 4; FUNCN: C_C.Normal_package; INSTANCENAME: INS17111037; NOTE: 1uF 10V; PART TYPE: Ceramic Capacitor; REFERENCE TEMPLATE: C; SIZE: 1; VAL1: 1uF(K); VAL2: 10V
C168 = C_v2: COMP: C-GRM1885C1H471JA01D; COMPONENTNAME: C_C.Normal_package; COMPONENTTYPE: 4; FUNCN: C_C.Normal_package; INSTANCENAME: INS17330257; NOTE: 470pF 50V; PART TYPE: Ceramic Capacitor; REFERENCE TEMPLATE: C; SIZE: 1; VAL1: 470pF(J); VAL2: 50V
C170 = C_v2: COMP: C-GRM1885C1H471JA01D; COMPONENTNAME: C_C.Normal_package; COMPONENTTYPE: 4; FUNCN: C_C.Normal_package; INSTANCENAME: INS17330365; NOTE: 470pF 50V; PART TYPE: Ceramic Capacitor; REFERENCE TEMPLATE: C; SIZE: 1; VAL1: 470pF(J); VAL2: 50V
C171 = C_v2: COMP: C-GRM1885C1H471JA01D; COMPONENTNAME: C_C.Normal_package; COMPONENTTYPE: 4; FUNCN: C_C.Normal_package; INSTANCENAME: INS17330483; NOTE: 470pF 50V; PART TYPE: Ceramic Capacitor; REFERENCE TEMPLATE: C; SIZE: 1; VAL1: 470pF(J); VAL2: 50V
C173 = C_v2: COMP: C-GRM1885C1H471JA01D; COMPONENTNAME: C_C.Normal_package; COMPONENTTYPE: 4; FUNCN: C_C.Normal_package; INSTANCENAME: INS17330591; NOTE: 470pF 50V; PART TYPE: Ceramic Capacitor; REFERENCE TEMPLATE: C; SIZE: 1; VAL1: 470pF(J); VAL2: 50V
C174 = C_v2: COMP: C-GRM188R71A105KA61D; COMPONENTNAME: C_C.Normal_package; COMPONENTTYPE: 4; FUNCN: C_C.Normal_package; INSTANCENAME: INS17336633; NOTE: 1uF 10V; PART TYPE: Ceramic Capacitor; REFERENCE TEMPLATE: C; SIZE: 1; SIZECODESMD: 1608; VAL1: 1uF(K); VAL2: 10V
C175 = C_v2: COMP: C-GRM188R71A105KA61D; COMPONENTNAME: C_C.Normal_package; COMPONENTTYPE: 4; FUNCN: C_C.Normal_package; INSTANCENAME: INS17330751; NOTE: 1uF 10V; PART TYPE: Ceramic Capacitor; REFERENCE TEMPLATE: C; SIZE: 1; VAL1: 1uF(K); VAL2: 10V
CT2 = F02P050S05L: COMP: CT-F02P050S05L; COMPONENTTYPE: 4
D56 = SBD: COMP: DSR01S30SL; COMPONENTTYPE: 4; USERCOMPTEXT3: TOSHIBA; VAL3: DSR01S30SL
D58 = D: COMP: D-DSR01S30SL; COMPONENTNAME: D_D.Normal_package; COMPONENTTYPE: 4; FUNCN: D_D.Normal_package; INSTANCENAME: INS17313401; NOTE: 30V 0.1A; PART NUMBER: TMP-433; PART TYPE: Schottky barrier Diode; USERCOMPTEXT3: TOSHIBA
IC1 IC24 = OPA4322AIPWR: COMP: IC-OPA4322AIPWR; COMPONENTTYPE: 4
IC20 = TLP7920_LF5: COMP: IC-TLP7920_LF5_TP5; COMPONENTTYPE: 4; USERCOMPTEXT3: TOSHIBA; VAL3: TLP7920
IC23 = REF2025AIDDCT: COMP: IC-REF2025AIDDCT; COMPONENTTYPE: 4
PS10 = R05P05S: COMP: PS-R05P05S; COMPONENTTYPE: 4
R120 = R: COMP: R-RK73G1JTTD3602F; COMPONENTNAME: R_R.Normal_package; COMPONENTTYPE: 4; FUNCN: R_R.Normal_package; INSTANCENAME: INS17110637; NOTE: 36kohm 0.1W; VAL1: 36k(F); VAL2: 100mw
R122 = R: COMP: R-RK73G1JTTD1202F; COMPONENTNAME: R_R.Normal_package; COMPONENTTYPE: 4; FUNCN: R_R.Normal_package; INSTANCENAME: INS17110687; NOTE: 12kohm 0.1W; VAL1: 12k(F); VAL2: 100mw
R123 = R: COMP: R-RK73G1JTTD1202F; COMPONENTNAME: R_R.Normal_package; COMPONENTTYPE: 4; FUNCN: R_R.Normal_package; INSTANCENAME: INS17110773; NOTE: 12kohm 0.1W; VAL1: 12k(F); VAL2: 100mw
R124 = R: COMP: R-ERJ3EKF1803V; COMPONENTNAME: R_R.Normal_package; COMPONENTTYPE: 4; FUNCN: R_R.Normal_package; INSTANCENAME: INS17190846; NOTE: 180kohm 0.1W; PART TYPE: Resistor SMD; SIZE: 1; VAL1: 180k(F); VAL2: 100mw
R125 = R: COMP: R-ERJ3EKF1803V; COMPONENTNAME: R_R.Normal_package; COMPONENTTYPE: 4; FUNCN: R_R.Normal_package; INSTANCENAME: INS17190954; NOTE: 180kohm 0.1W; PART TYPE: Resistor SMD; SIZE: 1; VAL1: 180k(F); VAL2: 100mw
R126 = R: COMP: R-ERJ3EKF1803V; COMPONENTNAME: R_R.Normal_package; COMPONENTTYPE: 4; FUNCN: R_R.Normal_package; INSTANCENAME: INS17191012; NOTE: 180kohm 0.1W; PART TYPE: Resistor SMD; SIZE: 1; VAL1: 180k(F); VAL2: 100mw
R127 = R: COMP: R-ERJ3EKF1803V; COMPONENTNAME: R_R.Normal_package; COMPONENTTYPE: 4; FUNCN: R_R.Normal_package; INSTANCENAME: INS17191162; NOTE: 180kohm 0.1W; PART TYPE: Resistor SMD; SIZE: 1; VAL1: 180k(F); VAL2: 100mw
R128 = R: COMP: R-ERJ3EKF1803V; COMPONENTNAME: R_R.Normal_package; COMPONENTTYPE: 4; FUNCN: R_R.Normal_package; INSTANCENAME: INS17191255; NOTE: 180kohm 0.1W; PART TYPE: Resistor SMD; SIZE: 1; VAL1: 180k(F); VAL2: 100mw
R129 = R: COMP: R-RK73G1JTTD3602F; COMPONENTNAME: R_R.Normal_package; COMPONENTTYPE: 4; FUNCN: R_R.Normal_package; INSTANCENAME: INS17110865; NOTE: 36kohm 0.1W; VAL1: 36k(F); VAL2: 100mw
R130 = R: COMP: R-RK73Z1JTTD; COMPONENTNAME: R_R.Normal_package; COMPONENTTYPE: 4; FUNCN: R_R.Normal_package; INSTANCENAME: INS17110931; NOTE: 0ohm 0.1W; PART TYPE: Resistor SMD; SIZE: 1; VAL1: 0
R131 = R: COMP: R-RK73G1JTTD3900F; COMPONENTNAME: R_R.Normal_package; COMPONENTTYPE: 4; FUNCN: R_R.Normal_package; INSTANCENAME: INS17191487; NOTE: 390ohm 0.1W; PART TYPE: Resistor SMD; SIZE: 1; VAL1: 390(F); VAL2: 100mw
R132 = R: COMP: R-RK73B2ATTD471J; COMPONENTNAME: R_R.Normal_package; COMPONENTTYPE: 4; FUNCN: R_R.Normal_package; INSTANCENAME: INS17417097; NOTE: 470ohm 0.25W; PART TYPE: Resistor SMD; SIZE: 1; VAL1: 470(J); VAL2: 250mw
R153 = R: COMP: R-RK73H1JTTD1002F; COMPONENTNAME: R_R.Normal_package; COMPONENTTYPE: 4; FUNCN: R_R.Normal_package; INSTANCENAME: INS17356570; NOTE: 10kohm 0.1W; VAL1: 10k(F); VAL2: 100mw
R154 = R: COMP: R-RK73H1JTTD1002F; COMPONENTNAME: R_R.Normal_package; COMPONENTTYPE: 4; FUNCN: R_R.Normal_package; INSTANCENAME: INS17356638; NOTE: 10kohm 0.1W; VAL1: 10k(F); VAL2: 100mw
R155 = R: COMP: R-RK73H1JTTD2002F; COMPONENTNAME: R_R.Normal_package; COMPONENTTYPE: 4; FUNCN: R_R.Normal_package; INSTANCENAME: INS17357275; NOTE: 20kohm 0.1W; VAL1: 20k(F); VAL2: 100mw
R156 = R: COMP: R-RK73H1JTTD2002F; COMPONENTNAME: R_R.Normal_package; COMPONENTTYPE: 4; FUNCN: R_R.Normal_package; INSTANCENAME: INS17357383; NOTE: 20kohm 0.1W; VAL1: 20k(F); VAL2: 100mw
R157 = R: COMP: R-RK73H1JTTD1002F; COMPONENTNAME: R_R.Normal_package; COMPONENTTYPE: 4; FUNCN: R_R.Normal_package; INSTANCENAME: INS17356770; NOTE: 10kohm 0.1W; VAL1: 10k(F); VAL2: 100mw
R158 = R: COMP: R-RK73H1JTTD2002F; COMPONENTNAME: R_R.Normal_package; COMPONENTTYPE: 4; FUNCN: R_R.Normal_package; INSTANCENAME: INS17357470; NOTE: 20kohm 0.1W; VAL1: 20k(F); VAL2: 100mw
R159 = R: COMP: R-RK73H1JTTD1002F; COMPONENTNAME: R_R.Normal_package; COMPONENTTYPE: 4; FUNCN: R_R.Normal_package; INSTANCENAME: INS17356836; NOTE: 10kohm 0.1W; VAL1: 10k(F); VAL2: 100mw
R160 = R: COMP: R-RK73H1JTTD2002F; COMPONENTNAME: R_R.Normal_package; COMPONENTTYPE: 4; FUNCN: R_R.Normal_package; INSTANCENAME: INS17357529; NOTE: 20kohm 0.1W; VAL1: 20k(F); VAL2: 100mw
TB7 = OP_057: COMP: TB-OP-057; COMPONENTNAME: OP-057_OP-057.Normal_package; COMPONENTTYPE: 4; FUNCN: OP-057_OP-057.Normal_package; INSTANCENAME: INS17364473; PART NUMBER: TMP-784; PART TYPE: Terminal Block; REFERENCE TEMPLATE: TB; SAVECOUNT: 1; UPDATETIME: 14:31:25
TB8 = OP_057: COMP: TB-OP-057; COMPONENTNAME: OP-057_OP-057.Normal_package; COMPONENTTYPE: 4; FUNCN: OP-057_OP-057.Normal_package; INSTANCENAME: INS17364565; PART NUMBER: TMP-784; PART TYPE: Terminal Block; REFERENCE TEMPLATE: TB; SAVECOUNT: 1; UPDATETIME: 14:31:25
U?#1 = WAKU_DEF100: COMPONENTTYPE: 2; DATE: 2026/04/27; DRAWINGNUMBER: RD264-SCHEMATIC-01; FUNCTION: current detection / & low-voltage side voltage detection; REVISION: 01; SHEETNUMBER: 6/7; SHTSAVECOUNT: 15; TITLE: Full SiC MOSFET 10kW Isolated / Bidirectional DC-DC Converter; UPDATEDATE: 2026.4.27; UPDATETIME: 14:22:34
C162 = C_v2: COMP: C-GRM31CR61H106KA12L; COMPONENTNAME: C_C.Normal_package; COMPONENTTYPE: 4; FUNCN: C_C.Normal_package; INSTANCENAME: INS17108792; NOTE: 10uF 50V; PART TYPE: Ceramic Capacitor; REFERENCE TEMPLATE: C; SIZE: 1; VAL1: 10uF(K); VAL2: 50V
C163 = C_v2: COMP: C-GRM31CR61H106KA12L; COMPONENTNAME: C_C.Normal_package; COMPONENTTYPE: 4; FUNCN: C_C.Normal_package; INSTANCENAME: INS17108358; NOTE: 10uF 50V; PART TYPE: Ceramic Capacitor; REFERENCE TEMPLATE: C; SIZE: 1; VAL1: 10uF(K); VAL2: 50V
C164 = C_v2: COMP: C-GRM188R71A105KA61D; COMPONENTNAME: C_C.Normal_package; COMPONENTTYPE: 4; FUNCN: C_C.Normal_package; INSTANCENAME: INS17108750; NOTE: 1uF 10V; PART TYPE: Ceramic Capacitor; REFERENCE TEMPLATE: C; SIZE: 1; VAL1: 1uF(K); VAL2: 10V
C165 = C_v2: COMP: C-GRM188R71A105KA61D; COMPONENTNAME: C_C.Normal_package; COMPONENTTYPE: 4; FUNCN: C_C.Normal_package; INSTANCENAME: INS17108480; NOTE: 1uF 10V; PART TYPE: Ceramic Capacitor; REFERENCE TEMPLATE: C; SIZE: 1; VAL1: 1uF(K); VAL2: 10V
C166 = C_v2: COMP: C-1608_NM; COMPONENTNAME: C_C.Normal_package; COMPONENTTYPE: 4; FUNCN: C_C.Normal_package; INSTANCENAME: INS17108770; NOTMOUNT: NOT MOUNT; PART TYPE: Ceramic Capacitor; REFERENCE TEMPLATE: C; SIZE: 1; SIZECODESMD: 1608
C167 = C_v2: COMP: C-1608_NM; COMPONENTNAME: C_C.Normal_package; COMPONENTTYPE: 4; FUNCN: C_C.Normal_package; INSTANCENAME: INS17108347; NOTMOUNT: NOT MOUNT; PART TYPE: Ceramic Capacitor; REFERENCE TEMPLATE: C; SIZE: 1; SIZECODESMD: 1608
CN2 = BM03B_PASS_TFT_LF__SN: COMP: CN-BM03B-PASS-TFT_LF_SN; COMPONENTNAME: BM03B-PASS-TFT(LF)(SN)_BM03B-PASS-TFT(LF)(SN).Normal_package; COMPONENTTYPE: 4; FUNCN: BM03B-PASS-TFT(LF)(SN)_BM03B-PASS-TFT(LF)(SN).Normal_package; INSTANCENAME: INS17108276; PART TYPE: PA Connector; REFERENCE TEMPLATE: CN; SAVECOUNT: 1; SIZE: 1; UPDATETIME: 14:31:24
CN3 = BM04B_PASS_TFT_LF__SN: COMP: CN-BM04B-PASS-TFT_LF_SN; COMPONENTNAME: BM04B-PASS-TFT(LF)(SN)_BM04B-PASS-TFT(LF)(SN).Normal_package; COMPONENTTYPE: 4; FUNCN: BM04B-PASS-TFT(LF)(SN)_BM04B-PASS-TFT(LF)(SN).Normal_package; INSTANCENAME: INS17108649; PART TYPE: PA Connector; REFERENCE TEMPLATE: CN; SAVECOUNT: 1; SIZE: 1; UPDATETIME: 14:31:24
CN4 = WR_60S_VFH05_N1: COMP: CN-WR-60S-VFH05-N1; COMPONENTNAME: WR-60S-VFH05-N1_WR-60S-VFH05-N1.Normal_package; COMPONENTTYPE: 4; FUNCN: WR-60S-VFH05-N1_WR-60S-VFH05-N1.Normal_package; INSTANCENAME: INS17108513; SAVECOUNT: 1; UPDATETIME: 14:31:24
IC21 IC22 = TC74VHC541F: COMP: IC-TC74VHC541FT; COMPONENTTYPE: 4; USERCOMPTEXT3: TOSHIBA
L1 = MBKK1608T1R0M: Common Mode Filters; COMP: L-MBKK1608T1R0M; COMPONENTNAME: MBKK1608T1R0M_MBKK1608T1R0M.Normal_package; COMPONENTTYPE: 4; FUNCN: MBKK1608T1R0M_MBKK1608T1R0M.Normal_package; INSTANCENAME: INS17108449; NOTE: 1.0uH±20% 0.8A; PART TYPE: Common mode Choke Coils; REFERENCE TEMPLATE: L; SIZE: 1
LED1 = VCDG1111C_4BY3C_TR: COMP: LED-VCDG1111C-4BY3C-TR; COMPONENTNAME: VCDG1111C-4BY3C-TR_VCDG1111C-4BY3C-TR.Normal_package; COMPONENTTYPE: 4; FUNCN: VCDG1111C-4BY3C-TR_VCDG1111C-4BY3C-TR.Normal_package; INSTANCENAME: INS17108814
PS11 = MGFS102405: COMP: PS-MGFS102405; COMPONENTNAME: MGFS102405_MGFS102405.Normal_package; COMPONENTTYPE: 4; FUNCN: MGFS102405_MGFS102405.Normal_package; INSTANCENAME: INS17108317; SAVECOUNT: 1; UPDATETIME: 14:31:24
R133 = R: COMP: R-RK73B1JTTD471J; COMPONENTNAME: R_R.Normal_package; COMPONENTTYPE: 4; FUNCN: R_R.Normal_package; INSTANCENAME: INS17266666; NOTE: 470ohm 0.1W; PART TYPE: Resistor SMD; SIZE: 1; VAL1: 470(J); VAL2: 125mw
R134 = R: COMP: R-RK73H1JTTD1002F; COMPONENTNAME: R_R.Normal_package; COMPONENTTYPE: 4; FUNCN: R_R.Normal_package; INSTANCENAME: INS17267993; NOTE: 10kohm 0.1W; VAL1: 10k(F); VAL2: 100mw
R135 = R: COMP: R-RK73H1JTTD1002F; COMPONENTNAME: R_R.Normal_package; COMPONENTTYPE: 4; FUNCN: R_R.Normal_package; INSTANCENAME: INS17268696; NOTE: 10kohm 0.1W; VAL1: 10k(F); VAL2: 100mw
R136 = R: COMP: R-RK73H1JTTD1002F; COMPONENTNAME: R_R.Normal_package; COMPONENTTYPE: 4; FUNCN: R_R.Normal_package; INSTANCENAME: INS17268983; NOTE: 10kohm 0.1W; VAL1: 10k(F); VAL2: 100mw
R137 = R: COMP: R-RK73H1JTTD1002F; COMPONENTNAME: R_R.Normal_package; COMPONENTTYPE: 4; FUNCN: R_R.Normal_package; INSTANCENAME: INS17269149; NOTE: 10kohm 0.1W; VAL1: 10k(F); VAL2: 100mw
R138 = R: COMP: R-RK73H1JTTD1002F; COMPONENTNAME: R_R.Normal_package; COMPONENTTYPE: 4; FUNCN: R_R.Normal_package; INSTANCENAME: INS17269317; NOTE: 10kohm 0.1W; VAL1: 10k(F); VAL2: 100mw
R139 = R: COMP: R-RK73H1JTTD1002F; COMPONENTNAME: R_R.Normal_package; COMPONENTTYPE: 4; FUNCN: R_R.Normal_package; INSTANCENAME: INS17269478; NOTE: 10kohm 0.1W; VAL1: 10k(F); VAL2: 100mw
R140 = R: COMP: R-RK73H1JTTD1002F; COMPONENTNAME: R_R.Normal_package; COMPONENTTYPE: 4; FUNCN: R_R.Normal_package; INSTANCENAME: INS17269639; NOTE: 10kohm 0.1W; VAL1: 10k(F); VAL2: 100mw
R141 = R: COMP: R-RK73H1JTTD1002F; COMPONENTNAME: R_R.Normal_package; COMPONENTTYPE: 4; FUNCN: R_R.Normal_package; INSTANCENAME: INS17269801; NOTE: 10kohm 0.1W; VAL1: 10k(F); VAL2: 100mw
R142 = R: COMP: R-RK73B1JTTD472J; COMPONENTNAME: R_R.Normal_package; COMPONENTTYPE: 4; FUNCN: R_R.Normal_package; INSTANCENAME: INS17108297; NOTE: 4.7kohm 0.1W; PART TYPE: Resistor SMD; SIZE: 1; VAL1: 4.7k(J); VAL2: 100mw
R143 = R: COMP: R-RK73B1JTTD472J; COMPONENTNAME: R_R.Normal_package; COMPONENTTYPE: 4; FUNCN: R_R.Normal_package; INSTANCENAME: INS17108672; NOTE: 4.7kohm 0.1W; PART TYPE: Resistor SMD; SIZE: 1; VAL1: 4.7k(J); VAL2: 100mw
R144 = R: COMP: R-ERJ3EKF1000V; COMPONENTNAME: R_R.Normal_package; COMPONENTTYPE: 4; FUNCN: R_R.Normal_package; INSTANCENAME: INS17108491; NOTE: 100ohm 0.1W; PART TYPE: Resistor SMD; SIZE: 1; VAL1: 100(F); VAL2: 100mw
R145 = R: COMP: R-ERJ3EKF1000V; COMPONENTNAME: R_R.Normal_package; COMPONENTTYPE: 4; FUNCN: R_R.Normal_package; INSTANCENAME: INS17108389; NOTE: 100ohm 0.1W; PART TYPE: Resistor SMD; SIZE: 1; VAL1: 100(F); VAL2: 100mw
U?#7 = WAKU_DEF100: COMPONENTTYPE: 2; DATE: 2026/04/27; DRAWINGNUMBER: RD264-SCHEMATIC-01; FUNCTION: DC-DC & PWM INPUT; REVISION: 01; SHEETNUMBER: 7/7; SHTSAVECOUNT: 12; TITLE: Full SiC MOSFET 10kW Isolated / Bidirectional DC-DC Converter; UPDATEDATE: 2026.4.27; UPDATETIME: 14:24:11

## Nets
+5V: C13.1 C119.1 C139.1 C146.1 C153.1 C160.1 C163.1 C164.1 C165.1 C172.1 C174.1 CN4.1 CN4.2 CN4.3 CN4.4 CT2.14(+5V) IC1.4(V+) IC16.2(VCC1) IC18.2(VCC1) IC20.8(VDD2) IC21.20(VCC) IC22.20(VCC) IC23.3(EN) IC23.4(VIN) IC24.4(V+) PS10.1(+VIN) PS11.6(VOUT+) R95.1 R107.1 R133.1 R134.1 R135.1 R136.1 R137.1 R138.1 R139.1 R140.1 R141.1 R142.1 R143.1 TP44.1 ; also on sheet 4 5 6 7
+5V_DC_SEC: C155.1 C161.1 D56.K(C) IC20.1(VDD1) PS10.7(+VOUT) R132.1
+12V_Q7: C117.1 C118.1 C120.1 C121.1 IC15.1(OUTPUT) IC16.13(VCC2) R92.1 R101.1 R102.1 R167.2 TP32.1
+12V_Q8: C137.1 C138.1 C140.1 C141.1 IC17.1(OUTPUT) IC18.13(VCC2) R104.1 R113.1 R114.1 R170.2 TP37.1
+24V: C114.1 C134.1 C162.1 CN2.1 CN3.1 CN3.3 L1.1 PS8.1(+VIN) PS9.1(+VIN) TP43.1 ; also on sheet 4 5 6
GND: C13.2 C119.2 C139.2 C146.2 C153.2 C159.1 C160.2 C163.2 C164.2 C165.2 C166.2 C167.2 C172.2 C174.2 C175.2 CN4.5 CN4.6 CN4.7 CN4.8 CN4.11 CN4.12 CN4.15 CN4.16 CN4.19 CN4.20 CN4.23 CN4.24 CN4.31 CN4.32 CN4.39 CN4.40 CN4.50 CN4.59 CN4.60 CT2.13(0V) IC1.11(V-) IC16.1(VS1) IC16.4(VS2) IC18.1(VS1) IC18.4(VS2) IC20.5(GND2) IC21.1(OE1) IC21.6(A5) IC21.7(A6) IC21.8(A7) IC21.9(A8) IC21.10(GND) IC21.19(OE2) IC22.1(OE1) IC22.8(A7) IC22.9(A8) IC22.10(GND) IC22.19(OE2) IC23.2(GND) IC24.11(V-) LED1.K PS10.2(-VIN) PS11.7(0V) R129.1 TP45.1 ; also on sheet 4 5 6 7
GND_24V: C114.2 C134.2 C162.2 CN2.3 CN3.2 CN3.4 PS8.2(-VIN) PS9.2(-VIN) PS11.1(GND) TP46.1 ; also on sheet 4 5 6
GND_DC_SEC: C155.2 C161.2 IC20.4(GND1) PS10.5(-VOUT) R130.2 R132.2
GND_Q7: C115.2 C116.2 C118.2 C120.2 C124.2 D48.A IC15.3(SHUTDOWN) IC15.4(GND) IC16.9(VEE1) IC16.12(VEE2) PS8.5(-VOUT) R94.2 R179.2 TP36.1
GND_Q8: C135.2 C136.2 C138.2 C140.2 C144.2 D54.A IC17.3(SHUTDOWN) IC17.4(GND) IC18.9(VEE1) IC18.12(VEE2) PS9.5(-VOUT) R106.2 R180.2 TP41.1
/DI0_BI: CN4.51 R144.2
/DI1_BI: CN4.52 R145.2
/FLT_OUT_HV: C167.1 IC22.6(A5) R142.2 TP55.1 ; also on sheet 5 6
/FLT_OUT_LV: C166.1 IC16.3(FLT) IC18.3(FLT) IC22.7(A6) R143.2 TP56.1 ; also on sheet 4
/PWM2A_BO: CN4.27 IC21.2(A1) R134.2
/PWM2B_BO: CN4.28 IC21.3(A2) R135.2
/PWM3A_BO: CN4.29 IC21.4(A3) R136.2
/PWM3B_BO: CN4.30 IC21.5(A4) R137.2
/PWM5A_BO: CN4.35 IC22.2(A1) R138.2
/PWM5B_BO: CN4.36 IC22.3(A2) R139.2
/PWM6A_BO: CN4.37 IC22.4(A3) R140.2
/PWM6B_BO: CN4.38 IC22.5(A4) R141.2
/PWM_2A: IC21.18(Y1) TP47.1 ; also on sheet 6
/PWM_2B: IC21.17(Y2) TP48.1 ; also on sheet 6
/PWM_3A: IC21.16(Y3) TP49.1 ; also on sheet 5
/PWM_3B: IC21.15(Y4) TP50.1 ; also on sheet 5
/PWM_5A: IC22.18(Y1) TP51.1 ; also on sheet 4
/PWM_5B: IC22.17(Y2) TP52.1 ; also on sheet 4
/PWM_6A: IC16.5(K1) IC16.8(K2) IC22.16(Y3) R99.2 TP53.1
/PWM_6B: IC18.5(K1) IC18.8(K2) IC22.15(Y4) R111.2 TP54.1
AD0: CN4.9 ; also on sheet 7
AD1: CN4.10 ; also on sheet 7
AD2: C168.2 CN4.13 IC1.14(OUTD) R155.1
AD3: C154.1 CN4.14 IC24.8(OUTC) R120.1
AD4: C171.2 CN4.17 IC24.14(OUTD) R158.1
HV_DC_CURRENT: IC1.5(+INB) ; also on sheet 7
HV_DC_CURRENT_REF: IC1.3(+INA) ; also on sheet 7
LV_DC_CURRENT: CT2.12(OUT) IC24.5(+INB) TP42.1
LV_DC_CURRENT_REF: CT2.11(Ref) IC24.3(+INA) TP58.1
LV_DC_N: C130.2 C131.2 C132.2 C133.2 C141.2 C142.2 C143.2 C144.1 C147.2 C148.2 C149.2 C150.2 C151.2 C152.2 C157.2 D52.A D53.A D54.K(C) D58.A D66.A1 D66.A3 IC18.16(VE) IC20.3(VIN-) Q8.S R113.2 R114.2 R115.2 R130.1 R131.2 R180.1 TB8.1 TB8.2 TB8.3 TB8.4 TP40.1 ; also on sheet 4
LV_DC_P: C126.1 C127.1 C128.1 C129.1 C147.1 C148.1 C149.1 C150.1 C151.1 C152.1 CT2.1 CT2.2 CT2.3 D43.K(C) D65.K2 Q7.D R128.1 ; also on sheet 4
SIG1: LED1.A R133.2
SIG6: L1.2 PS11.2(VIN)
SIG7: IC22.13(Y6) R145.1
SIG14: IC22.14(Y5) R144.1
SIG91: C170.1 IC1.12(+IND) R154.1 R156.2
SIG92: C170.2 C173.2 IC1.8(OUTC) IC1.9(-INC) R156.1 R160.1
SIG94: IC24.1(OUTA) IC24.2(-INA) R157.2
SIG97: C173.1 IC24.12(+IND) R159.1 R160.2
SIG99: C171.1 IC24.13(-IND) R157.1 R158.2
SIG103: IC20.6(VOUT-) R122.1
SIG104: R127.1 R128.2
SIG105: R124.1 R125.2
SIG106: C159.2 IC24.10(+INC) R123.2 R129.2
SIG107: R126.1 R127.2
SIG108: C157.1 D56.A D58.K(C) IC20.2(VIN+) R124.2 R131.1
SIG110: IC1.1(OUTA) IC1.2(-INA) R153.2
SIG111: R125.1 R126.2
SIG113: IC1.6(-INB) IC1.7(OUTB) R154.2
SIG114: CT2.8 CT2.9 CT2.10 TB7.1 TB7.2 TB7.3 TB7.4
SIG115: C154.2 IC24.9(-INC) R120.2 R122.2
SIG378: C168.1 IC1.13(-IND) R153.1 R155.2
SIG380: C175.1 IC1.10(+INC) IC23.5(VREF) TP59.1
SIG387: IC20.7(VOUT+) R123.1
SIG393: IC24.6(-INB) IC24.7(OUTB) R159.2
SIG482: IC16.6(A1) IC16.7(A2) R95.2 R99.1
SIG484: C121.2 C122.2 C123.2 C124.1 D46.A D47.A D48.K(C) D49.K(C) D65.A1 D65.A3 D66.K2 IC16.16(VE) Q7.S Q8.D R101.2 R102.2 R103.2 R179.1 TB6.1 TB6.2 TB6.3 TB6.4 TP35.1
SIG485: C115.1 C116.1 IC15.8(INPUT) R167.1 R168.2 R169.2
SIG489: C117.2 IC15.7(FEEDBACK) R93.2 R94.1
SIG490: C126.2 C127.2 C128.2 C129.2 C130.1 C131.1 C132.1 C133.1
SIG491: PS8.7(+VOUT) R168.1
SIG492: PS8.6(0V) R169.1
SIG493: IC16.11(Vout) R97.2 R98.2 R100.2
SIG494: D43.A R96.1
SIG496: C123.1 D45.A IC16.10(Vclamp) Q7.G R100.1 R103.1 TP34.1
SIG497: C142.1 D52.K(C) D53.K(C) IC18.14(DESAT) R108.2 R109.1 TP38.1
SIG498: PS9.6(0V) R172.1
SIG499: IC18.11(Vout) R109.2 R110.2 R112.2
SIG500: C143.1 D51.A IC18.10(Vclamp) Q8.G R112.1 R115.1 TP39.1
SIG502: D49.A R108.1
SIG504: C122.1 D46.K(C) D47.K(C) IC16.14(DESAT) R96.2 R97.1 TP33.1
SIG508: IC18.6(A1) IC18.7(A2) R107.2 R111.1
SIG509: D45.K(C) R98.1
SIG510: C135.1 C136.1 IC17.8(INPUT) R170.1 R171.2 R172.2
SIG512: PS9.7(+VOUT) R171.1
SIG513: C137.2 IC17.7(FEEDBACK) R105.2 R106.1
SIG514: R104.2 R105.1
SIG515: D51.K(C) R110.1
SIG520: R92.2 R93.1

Not connected (* = marked no-connect by the designer): CN2 2 NC1(P1) NC2(P2); CN3 NC1(P1) NC2(P2); CN4 18 21 22 25 26 33 34 41 42 43 44 45 46 47 48 49 53 54 55 56 57 58; IC15 2(SENSE) 5(ERROR) 6(VTAP); IC16 15(Vled); IC17 2(SENSE) 5(ERROR) 6(VTAP); IC18 15(Vled); IC21 11(Y8) 12(Y7) 13(Y6) 14(Y5); IC22 11(Y8) 12(Y7); IC23 1(VBIAS); PS10 6; PS11 3(Ctrl) 5(NC1) 8(NC2)

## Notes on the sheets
sheet 1
- 24Vin
- 1608
- 3216
- 3216
- 1608
- 1608
- 1608
- 1608
- FAN
- 1608
- BOARD to BOARD Connector
- 1608
- 1608
- 1608
- 1608
- 1608
- 1608
- 1608
- 1608
- 1608
sheet 2
- 1608
- 1608
- 1608
- 1608
- 1608
- 1608
- LV_DC_P
- 1608
- Idc_HV
- 1608
- 1608
- X6
- 1608
- 1608
- 1608
- 1608
- 1608
- 1608
- Idc_LV
- Vdc_LV
- 1608
- 1608
- 1608
- 1608
- 1608
- 1608X5
- 1608
- 1608
- 1608
- 1608
- 1608
- 1608
- 1608
- 2012
- 1608
- LV_DC_N
sheet 3
- 1608
- 2012
- 3216
- 1608
- 1608
- 3216
- 1608
- 1608
- 1608
- 1608
- 1608
- 1608
- 1608
- 1608
- 6432
- 1608
- 6432
- 1608
- 1608
- 1608
- 1608
- 2012
- L+
- 2012
- 1608
- 2012
- 3216
- 1608
- 1608
- 3216
- 1608
- 1608
- 1608
- 1608
- 1608
- 1608
- 1608
- 1608
- 6432
- 1608
- 6432
- 1608
- 1608
- 1608
- 1608
- 2012
- 2012
